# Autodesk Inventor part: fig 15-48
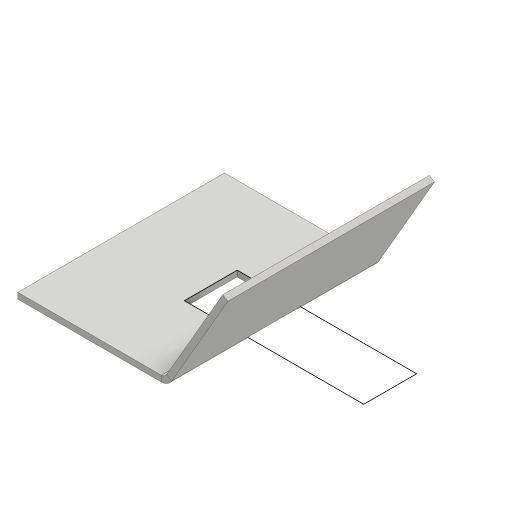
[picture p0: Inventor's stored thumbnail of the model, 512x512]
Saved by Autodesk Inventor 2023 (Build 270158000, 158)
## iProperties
Created: 2015-07
Part Number: fig 15-48
Material: Generic
Document SubType Name: Sheet Metal
Designer: Sandeep
Density: 1 g/cm^3
Sheet Metal Rule: Default_mm
Appearance: Default
Author: Sandeep
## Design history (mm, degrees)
node "Face1"
  sketch "Sketch1"
    geometry: L1 (-12.609, 8.313)-(0, 8.313); L2 (0, 8.313)-(0, -9.006); L3 (0, -9.006)-(-12.609, -9.006); L4 (-12.609, -9.006)-(-12.609, 8.313); 1 further point
    constraints: 8 end point, 2 parallel, 1 horizontal, 1 perpendicular
node "Flange1"
sketch "Sketch3"
  geometry: L1 (9.998, 1.795)-(-5.034, 1.795); L2 (-5.034, 1.795)-(-5.034, -2.633); L3 (-5.034, -2.633)-(9.998, -2.633); L4 (9.998, -2.633)-(9.998, 1.795); 1 further point
  constraints: 8 end point, 2 parallel, 1 horizontal, 1 perpendicular
cut "Cut1" sketch "Sketch3" dims "d11" = 0.5 (= Thickness), "d12" = 0
body "Solid1"
face "Plate1" dims "d13" = 0.5 (= Thickness)
sketch "Sketch2"
  geometry: L1 (0, 10)-(-17.319, 10); L2 (-17.319, 10)-(-17.319, 0); 1 other entity
  constraints: 4 end point, 4 other
face "Plate2" dims "d1" = 0.5 (= BendReliefWidth), "d2" = 0.25 (= BendReliefDepth), "d3" = 1 (= MinimumRemnant), "d4" = 0.5 (= BendRadius), "d5" = 10, "d6" = 60 deg, "d7" = 0.5 (= BendRadius), "d8" = 2 (= CornerReliefSize), "d9" = 0.5 (= GapSize), "d10" = 0.5 (= JacobiRadiusSize), "d13" = 0.5 (= Thickness), "SeamGap" = 0.01
bend "Bend1" dims "d1" = 0.5 (= BendReliefWidth), "d2" = 0.25 (= BendReliefDepth), "d3" = 1 (= MinimumRemnant), "d4" = 0.5 (= BendRadius), "d5" = 10, "d6" = 60 deg, "d7" = 0.5 (= BendRadius), "d13" = 0.5 (= Thickness), "SeamGap" = 0.01
feature "Corner1" dims "d5" = 10, "d6" = 60 deg, "d8" = 2 (= CornerReliefSize), "d9" = 0.5 (= GapSize), "d10" = 0.5 (= JacobiRadiusSize)
other parameters: "Thickness" = 0.5, "BendRadius" = 0.5 (= Thickness), "BendReliefWidth" = 0.5 (= Thickness), "BendReliefDepth" = 0.25 (= 0.5 x Thickness), "CornerReliefSize" = 2 (= 4 x Thickness), "MinimumRemnant" = 1 (= 2 x Thickness), "TransitionRadius" = 0.5 (= BendRadius), "JacobiRadiusSize" = 0.5 (= BendRadius), "GapSize" = 0.5 (= Thickness), "d0" = 0.5 (= BendRadius)
